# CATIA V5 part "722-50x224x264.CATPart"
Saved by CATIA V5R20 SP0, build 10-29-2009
Part number: 722-50x224x264
Definition: NONE
Nomenclature: 722-50x224x264
Source: Unknown
Description: 722-50x224x264
Bounding box of the stored display mesh (mm): x -25 to 25, y -24.818 to 24.818, z -206 to 58
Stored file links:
  C:\Users\Utente\Desktop\IO LAVORO\3D X SITO CF\X SITO\722\722-50x224x264.CATPart
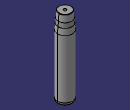
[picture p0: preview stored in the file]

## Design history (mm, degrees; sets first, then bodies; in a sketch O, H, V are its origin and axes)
Body1 "722-50x224x264" (main body)
  Solid1: solid without history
